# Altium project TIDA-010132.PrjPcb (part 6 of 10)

## Sheet POWER MAIN SHEET1.SchDoc
size 431 x 279 mm; Date: Not shown in title block; ApprovedBy: Not shown in title block; CheckedBy: Not shown in title block; Author: Not shown in title block; CompanyName: Not shown in title block; DrawnBy: Avinash N; Engineer: Not shown in title block; Organization: Not shown in title block; Address1: Not shown in title block; Address2: Not shown in title block; Address3: Not shown in title block; Address4: Not shown in title block; DocumentNumber: 1; Revision: Use project parameter SCH_Rev; SheetNumber: 30; SheetTotal: 32; PageSetup: Record=PageOptions¦CenterHorizontal=True¦CenterVertical=True¦PrintScale=1.00¦XCorrection=1.00¦YCorrection=1.00¦PrintKind=0¦BorderSize=5000000¦LeftOffset=0¦BottomOffset=0¦Orientation=2¦PaperLength=1000¦PaperWidth=1000¦Scale=100¦PaperSource=15¦PrintQuality=600¦MediaType=1¦DitherType=10¦PaperKind=Letter¦PrintScaleMode=1
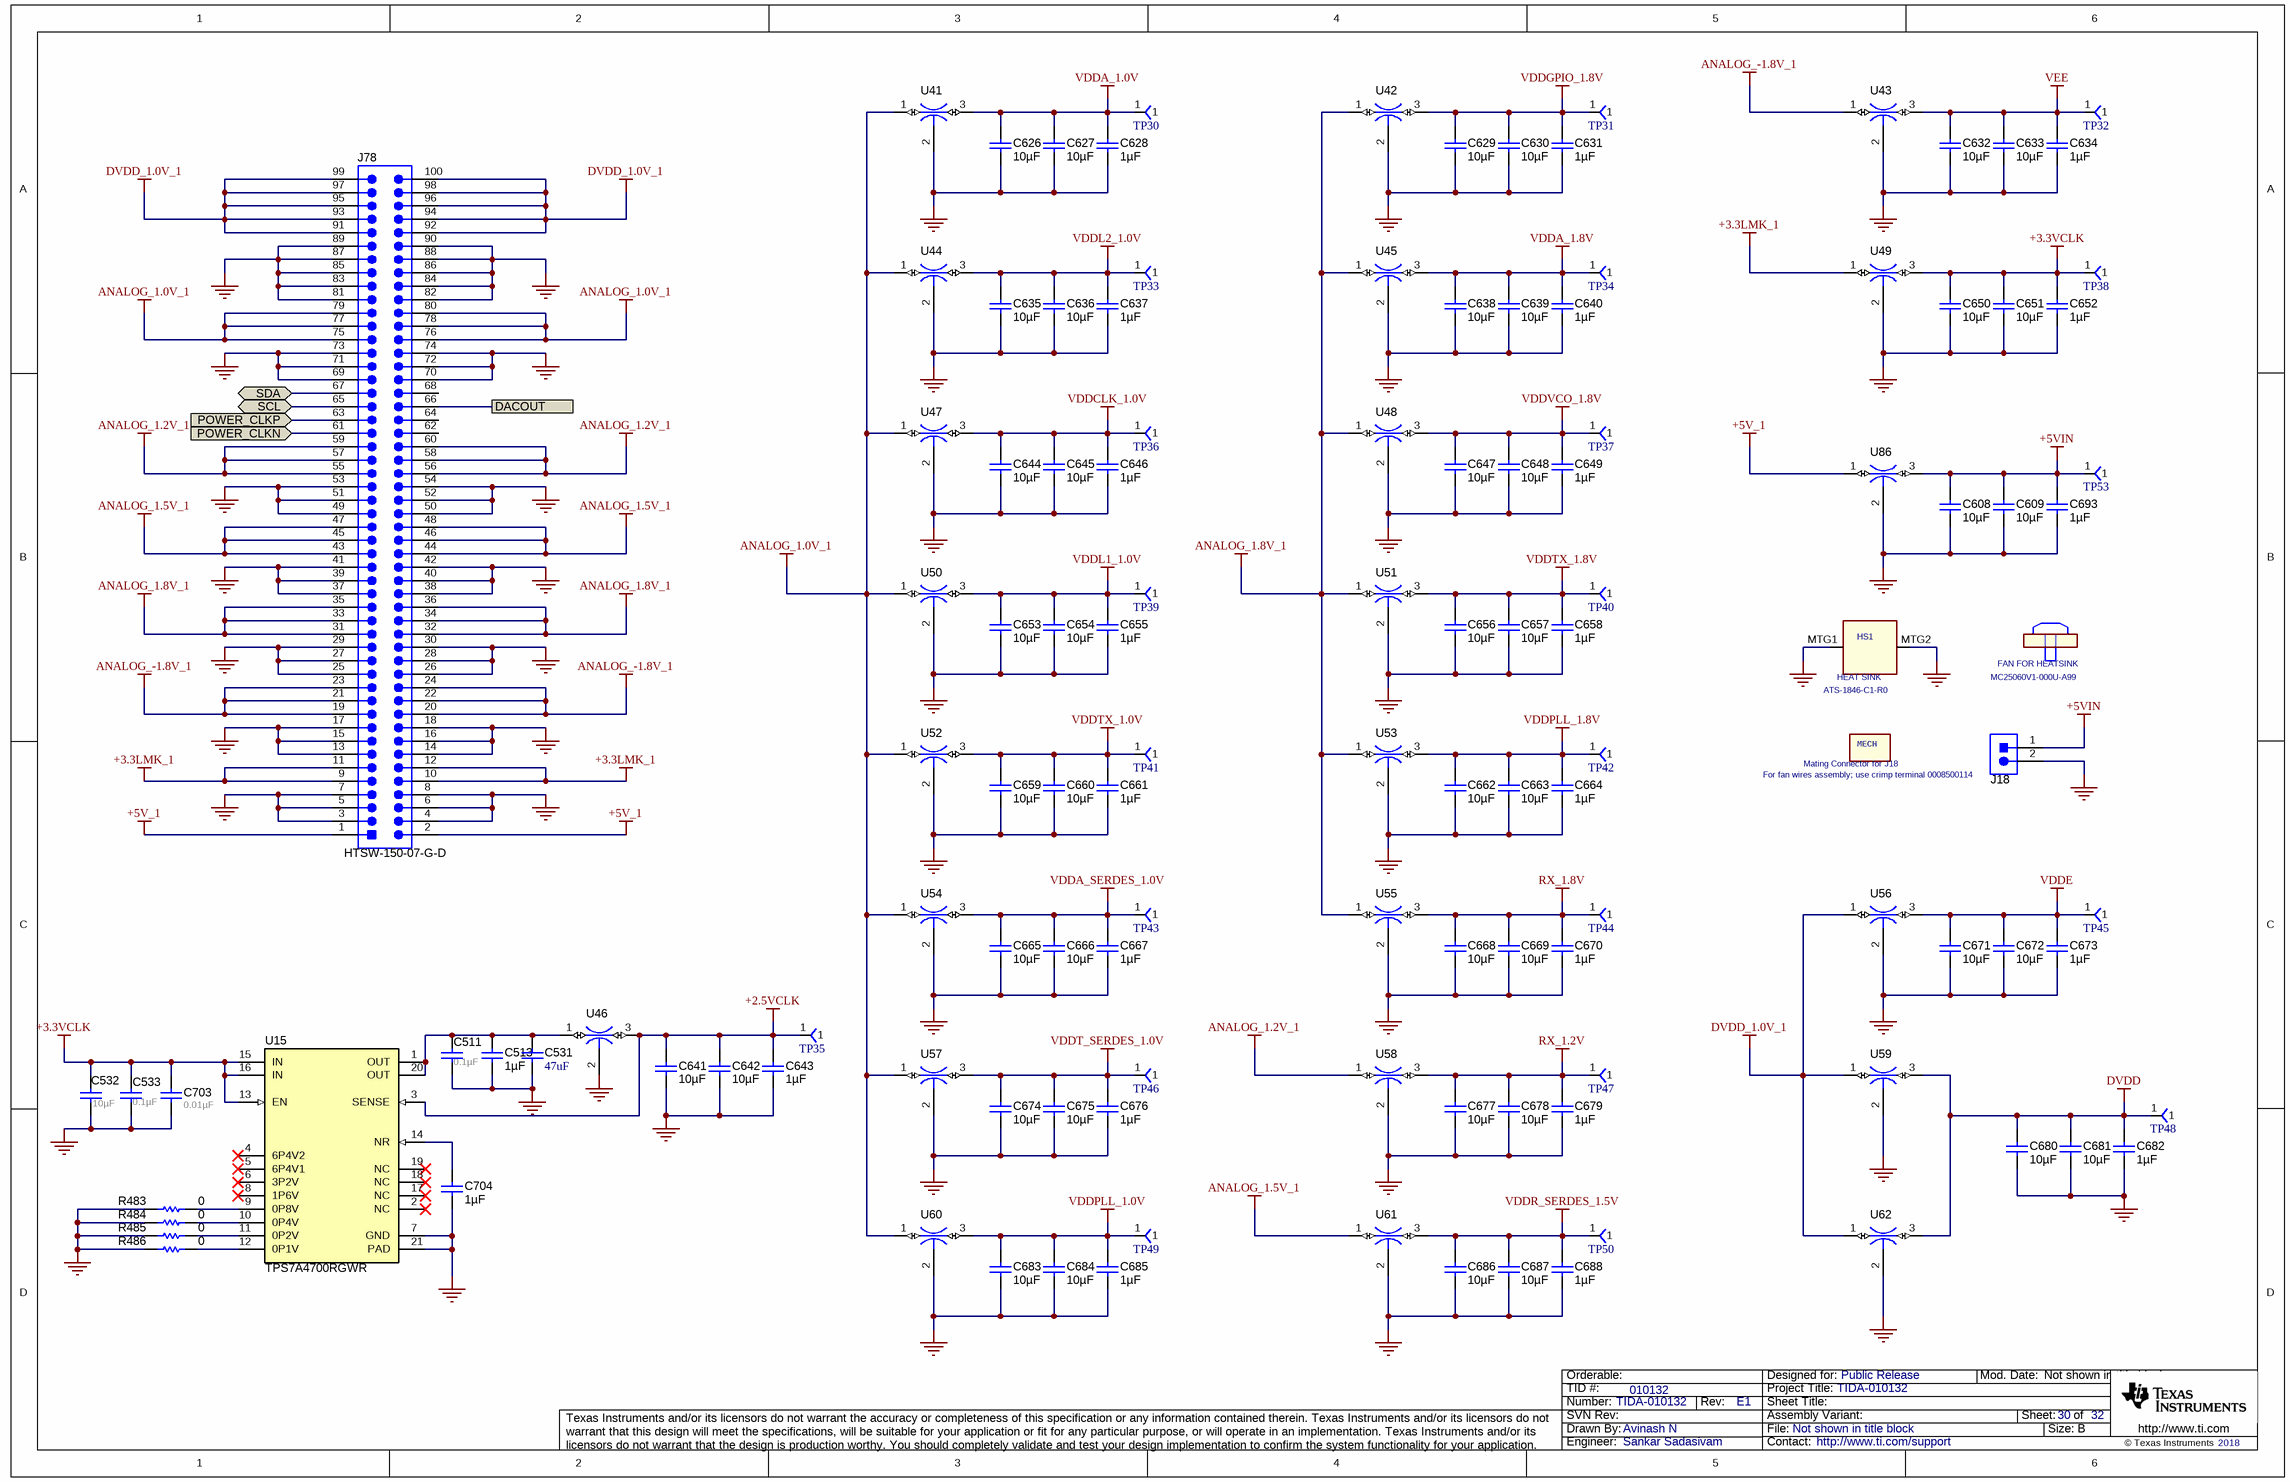
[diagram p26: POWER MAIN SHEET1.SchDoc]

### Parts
C511  ValueDisplayed: 0.1µF  [0603]  (hidden comment: 0603YC104JAT2A)
C513  ValueDisplayed: 1µF  [0603]  (hidden comment: C1608X7R1C105K080AC)
C531  value 47uF  [1210_270]  (hidden comment: GRM32ER61A476KE20L)
C532  ValueDisplayed: 10µF  [0805]  (hidden comment: C0805C106K8PACTU)
C533  ValueDisplayed: 0.1µF  [0603]  (hidden comment: 0603YC104JAT2A)
C608  ValueDisplayed: 10µF  [1206_190]  (hidden comment: C3216X7R1E106M160AE)
C609  ValueDisplayed: 10µF  [1206_190]  (hidden comment: C3216X7R1E106M160AE)
C626  ValueDisplayed: 10µF  [1206_190]  (hidden comment: C3216X7R1E106M160AE)
C627  ValueDisplayed: 10µF  [1206_190]  (hidden comment: C3216X7R1E106M160AE)
C628  ValueDisplayed: 1µF  [0603]  (hidden comment: C1608X7R1C105K080AC)
C629  ValueDisplayed: 10µF  [1206_190]  (hidden comment: C3216X7R1E106M160AE)
C630  ValueDisplayed: 10µF  [1206_190]  (hidden comment: C3216X7R1E106M160AE)
C631  ValueDisplayed: 1µF  [0603]  (hidden comment: C1608X7R1C105K080AC)
C632  ValueDisplayed: 10µF  [1206_190]  (hidden comment: C3216X7R1E106M160AE)
C633  ValueDisplayed: 10µF  [1206_190]  (hidden comment: C3216X7R1E106M160AE)
C634  ValueDisplayed: 1µF  [0603]  (hidden comment: C1608X7R1C105K080AC)
C635  ValueDisplayed: 10µF  [1206_190]  (hidden comment: C3216X7R1E106M160AE)
C636  ValueDisplayed: 10µF  [1206_190]  (hidden comment: C3216X7R1E106M160AE)
C637  ValueDisplayed: 1µF  [0603]  (hidden comment: C1608X7R1C105K080AC)
C638  ValueDisplayed: 10µF  [1206_190]  (hidden comment: C3216X7R1E106M160AE)
C639  ValueDisplayed: 10µF  [1206_190]  (hidden comment: C3216X7R1E106M160AE)
C640  ValueDisplayed: 1µF  [0603]  (hidden comment: C1608X7R1C105K080AC)
C641  ValueDisplayed: 10µF  [1206_190]  (hidden comment: C3216X7R1E106M160AE)
C642  ValueDisplayed: 10µF  [1206_190]  (hidden comment: C3216X7R1E106M160AE)
C643  ValueDisplayed: 1µF  [0603]  (hidden comment: C1608X7R1C105K080AC)
C644  ValueDisplayed: 10µF  [1206_190]  (hidden comment: C3216X7R1E106M160AE)
C645  ValueDisplayed: 10µF  [1206_190]  (hidden comment: C3216X7R1E106M160AE)
C646  ValueDisplayed: 1µF  [0603]  (hidden comment: C1608X7R1C105K080AC)
C647  ValueDisplayed: 10µF  [1206_190]  (hidden comment: C3216X7R1E106M160AE)
C648  ValueDisplayed: 10µF  [1206_190]  (hidden comment: C3216X7R1E106M160AE)
C649  ValueDisplayed: 1µF  [0603]  (hidden comment: C1608X7R1C105K080AC)
C650  ValueDisplayed: 10µF  [1206_190]  (hidden comment: C3216X7R1E106M160AE)
C651  ValueDisplayed: 10µF  [1206_190]  (hidden comment: C3216X7R1E106M160AE)
C652  ValueDisplayed: 1µF  [0603]  (hidden comment: C1608X7R1C105K080AC)
C653  ValueDisplayed: 10µF  [1206_190]  (hidden comment: C3216X7R1E106M160AE)
C654  ValueDisplayed: 10µF  [1206_190]  (hidden comment: C3216X7R1E106M160AE)
C655  ValueDisplayed: 1µF  [0603]  (hidden comment: C1608X7R1C105K080AC)
C656  ValueDisplayed: 10µF  [1206_190]  (hidden comment: C3216X7R1E106M160AE)
C657  ValueDisplayed: 10µF  [1206_190]  (hidden comment: C3216X7R1E106M160AE)
C658  ValueDisplayed: 1µF  [0603]  (hidden comment: C1608X7R1C105K080AC)
C659  ValueDisplayed: 10µF  [1206_190]  (hidden comment: C3216X7R1E106M160AE)
C660  ValueDisplayed: 10µF  [1206_190]  (hidden comment: C3216X7R1E106M160AE)
C661  ValueDisplayed: 1µF  [0603]  (hidden comment: C1608X7R1C105K080AC)
C662  ValueDisplayed: 10µF  [1206_190]  (hidden comment: C3216X7R1E106M160AE)
C663  ValueDisplayed: 10µF  [1206_190]  (hidden comment: C3216X7R1E106M160AE)
C664  ValueDisplayed: 1µF  [0603]  (hidden comment: C1608X7R1C105K080AC)
C665  ValueDisplayed: 10µF  [1206_190]  (hidden comment: C3216X7R1E106M160AE)
C666  ValueDisplayed: 10µF  [1206_190]  (hidden comment: C3216X7R1E106M160AE)
C667  ValueDisplayed: 1µF  [0603]  (hidden comment: C1608X7R1C105K080AC)
C668  ValueDisplayed: 10µF  [1206_190]  (hidden comment: C3216X7R1E106M160AE)
C669  ValueDisplayed: 10µF  [1206_190]  (hidden comment: C3216X7R1E106M160AE)
C670  ValueDisplayed: 1µF  [0603]  (hidden comment: C1608X7R1C105K080AC)
C671  ValueDisplayed: 10µF  [1206_190]  (hidden comment: C3216X7R1E106M160AE)
C672  ValueDisplayed: 10µF  [1206_190]  (hidden comment: C3216X7R1E106M160AE)
C673  ValueDisplayed: 1µF  [0603]  (hidden comment: C1608X7R1C105K080AC)
C674  ValueDisplayed: 10µF  [1206_190]  (hidden comment: C3216X7R1E106M160AE)
C675  ValueDisplayed: 10µF  [1206_190]  (hidden comment: C3216X7R1E106M160AE)
C676  ValueDisplayed: 1µF  [0603]  (hidden comment: C1608X7R1C105K080AC)
C677  ValueDisplayed: 10µF  [1206_190]  (hidden comment: C3216X7R1E106M160AE)
C678  ValueDisplayed: 10µF  [1206_190]  (hidden comment: C3216X7R1E106M160AE)
C679  ValueDisplayed: 1µF  [0603]  (hidden comment: C1608X7R1C105K080AC)
C680  ValueDisplayed: 10µF  [1206_190]  (hidden comment: C3216X7R1E106M160AE)
C681  ValueDisplayed: 10µF  [1206_190]  (hidden comment: C3216X7R1E106M160AE)
C682  ValueDisplayed: 1µF  [0603]  (hidden comment: C1608X7R1C105K080AC)
C683  ValueDisplayed: 10µF  [1206_190]  (hidden comment: C3216X7R1E106M160AE)
C684  ValueDisplayed: 10µF  [1206_190]  (hidden comment: C3216X7R1E106M160AE)
C685  ValueDisplayed: 1µF  [0603]  (hidden comment: C1608X7R1C105K080AC)
C686  ValueDisplayed: 10µF  [1206_190]  (hidden comment: C3216X7R1E106M160AE)
C687  ValueDisplayed: 10µF  [1206_190]  (hidden comment: C3216X7R1E106M160AE)
C688  ValueDisplayed: 1µF  [0603]  (hidden comment: C1608X7R1C105K080AC)
C693  ValueDisplayed: 1µF  [0603]  (hidden comment: C1608X7R1C105K080AC)
C703  ValueDisplayed: 0.01µF  [0402_065]  (hidden comment: 520L103KT16T)
C704  ValueDisplayed: 1µF  [0603]  (hidden comment: C1608X7R1C105K080AC)
CONN_HOUS_1  Mating Connector for J18  Note: For fan wires assembly; use crimp terminal 0008500114  (mechanical)
HS1  HEAT SINK  PartNumber: ATS-1846-C1-R0  [HEATSINK_27X27MM_ATS]
J18  TSW-102-07-T-S  [Samtec_TSW-102-07-T-S]  (value not drawn)
J78  HTSW-150-07-G-D  [Samtec_HTSW-150-07-x-D]
R483  ValueDisplayed: 0  [0402]  (hidden comment: ERJ-2GE0R00X)
R484  ValueDisplayed: 0  [0402]  (hidden comment: ERJ-2GE0R00X)
R485  ValueDisplayed: 0  [0402]  (hidden comment: ERJ-2GE0R00X)
R486  ValueDisplayed: 0  [0402]  (hidden comment: ERJ-2GE0R00X)
TP30  TP-025-SMT  [TP_25MIL-SMT]  (value not drawn)
TP31  TP-025-SMT  [TP_25MIL-SMT]  (value not drawn)
TP32  TP-025-SMT  [TP_25MIL-SMT]  (value not drawn)
TP33  TP-025-SMT  [TP_25MIL-SMT]  (value not drawn)
TP34  TP-025-SMT  [TP_25MIL-SMT]  (value not drawn)
TP35  TP-025-SMT  [TP_25MIL-SMT]  (value not drawn)
TP36  TP-025-SMT  [TP_25MIL-SMT]  (value not drawn)
TP37  TP-025-SMT  [TP_25MIL-SMT]  (value not drawn)
TP38  TP-025-SMT  [TP_25MIL-SMT]  (value not drawn)
TP39  TP-025-SMT  [TP_25MIL-SMT]  (value not drawn)
TP40  TP-025-SMT  [TP_25MIL-SMT]  (value not drawn)
TP41  TP-025-SMT  [TP_25MIL-SMT]  (value not drawn)
TP42  TP-025-SMT  [TP_25MIL-SMT]  (value not drawn)
TP43  TP-025-SMT  [TP_25MIL-SMT]  (value not drawn)
TP44  TP-025-SMT  [TP_25MIL-SMT]  (value not drawn)
TP45  TP-025-SMT  [TP_25MIL-SMT]  (value not drawn)
TP46  TP-025-SMT  [TP_25MIL-SMT]  (value not drawn)
TP47  TP-025-SMT  [TP_25MIL-SMT]  (value not drawn)
TP48  TP-025-SMT  [TP_25MIL-SMT]  (value not drawn)
TP49  TP-025-SMT  [TP_25MIL-SMT]  (value not drawn)
TP50  TP-025-SMT  [TP_25MIL-SMT]  (value not drawn)
TP53  TP-025-SMT  [TP_25MIL-SMT]  (value not drawn)
U15  TPS7A4700RGWR  [RGW0020A]
U41  NFM31PC276B0J3L  [Murata_NFM31P]  (value not drawn)
U42  NFM31PC276B0J3L  [Murata_NFM31P]  (value not drawn)
U43  NFM31PC276B0J3L  [Murata_NFM31P]  (value not drawn)
U44  NFM31PC276B0J3L  [Murata_NFM31P]  (value not drawn)
U45  NFM31PC276B0J3L  [Murata_NFM31P]  (value not drawn)
U46  NFM31PC276B0J3L  [Murata_NFM31P]  (value not drawn)
U47  NFM31PC276B0J3L  [Murata_NFM31P]  (value not drawn)
U48  NFM31PC276B0J3L  [Murata_NFM31P]  (value not drawn)
U49  NFM31PC276B0J3L  [Murata_NFM31P]  (value not drawn)
U50  NFM31PC276B0J3L  [Murata_NFM31P]  (value not drawn)
U51  NFM31PC276B0J3L  [Murata_NFM31P]  (value not drawn)
U52  NFM31PC276B0J3L  [Murata_NFM31P]  (value not drawn)
U53  NFM31PC276B0J3L  [Murata_NFM31P]  (value not drawn)
U54  NFM31PC276B0J3L  [Murata_NFM31P]  (value not drawn)
U55  NFM31PC276B0J3L  [Murata_NFM31P]  (value not drawn)
U56  NFM31PC276B0J3L  [Murata_NFM31P]  (value not drawn)
U57  NFM31PC276B0J3L  [Murata_NFM31P]  (value not drawn)
U58  NFM31PC276B0J3L  [Murata_NFM31P]  (value not drawn)
U59  NFM31PC276B0J3L  [Murata_NFM31P]  (value not drawn)
U60  NFM31PC276B0J3L  [Murata_NFM31P]  (value not drawn)
U61  NFM31PC276B0J3L  [Murata_NFM31P]  (value not drawn)
U62  NFM31PC276B0J3L  [Murata_NFM31P]  (value not drawn)
U86  NFM31PC276B0J3L  [Murata_NFM31P]  (value not drawn)
Z_FANHEATSINK1  FAN FOR HEATSINK  PartNumber: MC25060V1-000U-A99  (mechanical)

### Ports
DACOUT, POWER_CLKN (in), POWER_CLKP (in), SCL (bidir), SDA (bidir)

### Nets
+2.5VCLK: C641.2 C642.2 C643.2 TP35.1 U15.3(SENSE) U46.3
+3.3LMK_1: J78.9 J78.10 J78.11 J78.12 U49.1
+3.3VCLK: C532.2 C533.2 C650.2 C651.2 C652.2 C703.1 TP38.1 U15.13(EN) U15.15(IN) U15.16(IN) U49.3
+5V_1: J78.1 J78.2 U86.1
+5VIN: C608.2 C609.2 C693.2 J18.1 TP53.1 U86.3
ANALOG_1.0V_1: J78.75 J78.76 J78.77 J78.78 J78.79 J78.80 U41.1 U44.1 U47.1 U50.1 U52.1 U54.1 U57.1 U60.1
ANALOG_1.2V_1: J78.55 J78.56 J78.57 J78.58 J78.59 J78.60 U58.1
ANALOG_1.5V_1: J78.43 J78.44 J78.45 J78.46 J78.47 J78.48 U61.1
ANALOG_1.8V_1: J78.31 J78.32 J78.33 J78.34 J78.35 J78.36 U42.1 U45.1 U48.1 U51.1 U53.1 U55.1
ANALOG_-1.8V_1: J78.19 J78.20 J78.21 J78.22 J78.23 J78.24 U43.1
DVDD: C680.2 C681.2 C682.2 TP48.1 U59.3 U62.3
DVDD_1.0V_1: J78.91 J78.92 J78.93 J78.94 J78.95 J78.96 J78.97 J78.98 J78.99 J78.100 U56.1 U59.1 U62.1
GND: C511.1 C513.1 C531.2 C532.1 C533.1 C608.1 C609.1 C626.1 C627.1 C628.1 C629.1 C630.1 C631.1 C632.1 C633.1 C634.1 C635.1 C636.1 C637.1 C638.1 C639.1 C640.1 C641.1 C642.1 C643.1 C644.1 C645.1 C646.1 C647.1 C648.1 C649.1 C650.1 C651.1 C652.1 C653.1 C654.1 C655.1 C656.1 C657.1 C658.1 C659.1 C660.1 C661.1 C662.1 C663.1 C664.1 C665.1 C666.1 C667.1 C668.1 C669.1 C670.1 C671.1 C672.1 C673.1 C674.1 C675.1 C676.1 C677.1 C678.1 C679.1 C680.1 C681.1 C682.1 C683.1 C684.1 C685.1 C686.1 C687.1 C688.1 C693.1 C703.2 C704.1 HS1.MTG1 HS1.MTG2 J18.2 J78.3 J78.4 J78.5 J78.6 J78.7 J78.8 J78.13 J78.14 J78.15 J78.16 J78.17 J78.18 J78.25 J78.26 J78.27 J78.28 J78.29 J78.30 J78.37 J78.38 J78.39 J78.40 J78.41 J78.42 J78.49 J78.50 J78.51 J78.52 J78.53 J78.54 J78.69 J78.70 J78.71 J78.72 J78.73 J78.74 J78.81 J78.82 J78.83 J78.84 J78.85 J78.86 J78.87 J78.88 J78.89 J78.90 R483.1 R484.1 R485.1 R486.1 U15.7(GND) U15.21(PAD) U41.2 U42.2 U43.2 U44.2 U45.2 U46.2 U47.2 U48.2 U49.2 U50.2 U51.2 U52.2 U53.2 U54.2 U55.2 U56.2 U57.2 U58.2 U59.2 U60.2 U61.2 U62.2 U86.2
RX_1.2V: C677.2 C678.2 C679.2 TP47.1 U58.3
RX_1.8V: C668.2 C669.2 C670.2 TP44.1 U55.3
VDDA_1.0V: C626.2 C627.2 C628.2 TP30.1 U41.3
VDDA_1.8V: C638.2 C639.2 C640.2 TP34.1 U45.3
VDDA_SERDES_1.0V: C665.2 C666.2 C667.2 TP43.1 U54.3
VDDCLK_1.0V: C644.2 C645.2 C646.2 TP36.1 U47.3
VDDE: C671.2 C672.2 C673.2 TP45.1 U56.3
VDDGPIO_1.8V: C629.2 C630.2 C631.2 TP31.1 U42.3
VDDL1_1.0V: C653.2 C654.2 C655.2 TP39.1 U50.3
VDDL2_1.0V: C635.2 C636.2 C637.2 TP33.1 U44.3
VDDPLL_1.0V: C683.2 C684.2 C685.2 TP49.1 U60.3
VDDPLL_1.8V: C662.2 C663.2 C664.2 TP42.1 U53.3
VDDR_SERDES_1.5V: C686.2 C687.2 C688.2 TP50.1 U61.3
VDDT_SERDES_1.0V: C674.2 C675.2 C676.2 TP46.1 U57.3
VDDTX_1.0V: C659.2 C660.2 C661.2 TP41.1 U52.3
VDDTX_1.8V: C656.2 C657.2 C658.2 TP40.1 U51.3
VDDVCO_1.8V: C647.2 C648.2 C649.2 TP37.1 U48.3
VEE: C632.2 C633.2 C634.2 TP32.1 U43.3
DACOUT: J78.66 ; port DACOUT
POWER_CLKN: J78.61 ; port POWER_CLKN
POWER_CLKP: J78.63 ; port POWER_CLKP
SCL: J78.65 ; port SCL
SDA: J78.67 ; port SDA
NetC511_2: C511.2 C513.2 C531.1 U15.1(OUT) U15.20(OUT) U46.1
NetC704_2: C704.2 U15.14(NR)
NetR483_2: R483.2 U15.9(0P8V)
NetR484_2: R484.2 U15.10(0P4V)
NetR485_2: R485.2 U15.11(0P2V)
NetR486_2: R486.2 U15.12(0P1V)

Not connected (* = marked no-connect by the designer): J78 62 64 68; U15 2(NC)* 4(6P4V2)* 5(6P4V1)* 6(3P2V)* 8(1P6V)* 17(NC)* 18(NC)* 19(NC)*

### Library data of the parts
C511 C533 = 0603YC104JAT2A: CAP, CERM, 0.1uF, 16V, +/-5%, X7R, 0603; Manufacturer: AVX; ESR_Ohm: 0.039; Polarized: N; TaMax_C: 125; TaMin_C: -55; Tolerance_%: 5; VDC_V: 16; Cap_F: 0.0000001; CompType: Capacitor; Value1: 0.039 ohm; U/M: EA
C513 C628 C631 C634 C637 C640 C643 C646 C649 C652 C655 C658 C661 C664 C667 C670 C673 C676 C679 C682 C685 C688 C693 C704 = C1608X7R1C105K080AC: CAP, CERM, 1 µF, 16 V,+/- 10%, X7R, 0603; Manufacturer: TDK; Polarized: N; CompType: Capacitor; Value: 1uF; U/M: EA; Cap_F: 0.000001; Tolerance_%: 10; ESR_ohm: 0.0057; Value1: 0.0057 ohm; VDC_V: 16; Value2: 16V; TaMin_C: -55; TaMax_C: 125; SizeArea_mm2: 1.28; SizeAreaWB_mm2: 4.68; SizeX_mm: 1.6; SizeY_mm: 0.8; SizeZ_mm: 1; AEC Category: Q200; Green_Lifecycle: Active; Green_REACh: Passed
C531 = CMP-0009208-2: CAP, CERM, 47 uF, 10 V, +/- 10%, X5R, 1210; Manufacturer: MuRata; TaMin_C: -55°C; ESR_ohm: 1m; Polarized: N; SizeAreaWB_mm2: 14.7; Value1: 0.001 ohm; U/M: EA; TaMax_C: 85°C; SizeZ_mm: 2.7; SizeX_mm: 3.2; SizeY_mm: 2.5; Cap_Case: 1210; Value2: 10V; SizeArea_mm2: 8; CompType: Capacitor; Cap_F: 47µF; AEC Category: Q200
C532 = C0805C106K8PACTU: CAP, CERM, 10uF, 10V, +/-10%, X5R, 0805; Manufacturer: Kemet; ESR_Ohm: 0.003; IRMS_A: 11.43; Polarized: N; TaMax_C: 85; TaMin_C: -55; Tolerance_%: 10; Cap_F: 0.00001; CompType: Capacitor; U/M: EA; Value1: 0.003 ohm
C608 C609 C626 C627 C629 C630 C632 C633 C635 C636 C638 C639 C641 C642 C644 C645 C647 C648 C650 C651 C653 C654 C656 C657 C659 C660 C662 C663 C665 C666 C668 C669 C671 C672 C674 C675 C677 C678 C680 C681 C683 C684 C686 C687 = C3216X7R1E106M160AE: CAP, CERM, 10 µF, 25 V, +/- 20%, X7R, 1206_190; Manufacturer: TDK; Polarized: N; CompType: Capacitor; Value: 10uF; U/M: EA; Cap_F: 0.00001; Tolerance_%: 20; Value1: Unknown; VDC_V: 25; Value2: 25V; TaMin_C: -55; TaMax_C: 125; Cap_Case: 1206; SizeArea_mm2: 5.12; SizeAreaWB_mm2: 10.92; SizeX_mm: 3.2; SizeY_mm: 1.6; SizeZ_mm: 1.9; AEC Category: Q200
C703 = 520L103KT16T: CAP, CERM, 0.01 µF, 16 V, +/- 10%, X7R, 0402; Manufacturer: AT Ceramics; Polarized: N; CompType: Capacitor; Value: 0.01uF; U/M: EA; Cap_F: 0.00000001; Tolerance_%: 10; Value1: Unknown; VDC_V: 16; Value2: 16V; TaMin_C: -55; TaMax_C: 125; Cap_Case: 0402; AEC Category: Q200; SizeArea_mm2: 0.5; SizeAreaWB_mm2: 3; SizeX_mm: 1; SizeZ_mm: 0.65
CONN_HOUS_1 = MechPart: CONN HOUS 2POS .100 W/RAMP/RIB; Manufacturer: Molex
HS1 = HEATSINK_1: 1/2 BRICK HEATSINK 58X61X11.4MM; Manufacturer: Advanced Thermal Solutions
J18 = TSW-102-07-T-S: Header, 2.54 mm, 2x1, Tin, TH; Manufacturer: Samtec; SymbolCreator: a0412235; Pitch_mm: 2.54; Gender: Male; Shrouded: N; Row_Count: 1; Current_A: 6.3; Voltage_V: 550; Cert_CSA: Y; Green_Lifecycle: Active; Green_REACh: Passed
J78 = HTSW-150-07-G-D: Header, 2.54mm, 50x2, Gold, TH; Manufacturer: Samtec; SymbolCreator: a0799628; Pitch_mm: 2.54; Gender: Male; Shrouded: N; Row_Count: 2; Cert_CSA: Y; Green_Lifecycle: Active; Green_REACh: Passed
R483-R486 = ERJ-2GE0R00X: RES, 0, 5%, 0.063 W, 0402; Manufacturer: Panasonic; CompType: Resistor; Value: 0; Value_Code: 0000; Tolerance_%: 5; Power_W: 0.063; Value2: 0.063W; VDC_V: 50; TempCo: 600 ppm/C; SizeArea_mm2: 0.5; SizeX_mm: 1; SizeZ_mm: 0.6; EIA_Code: E24; U/M: EA; AEC Category: Q200; Green_Lifecycle: Active; Green_REACh: Passed
TP30-TP50 TP53 = TP-025-SMT: Test Point, O.025"; Manufacturer: STD; Value: STD
U15 = CMP-0066918-2: 36-V, 1-A, 4.17-uVRMS, RF LDO Voltage Regulator, RGW0020A (VQFN-20); Alternate PartNumber: TPS7A4700RGWT; Alternate Manufacturer: Texas Instruments; Green_Lifecycle: Active; SizeAreaWB_mm2: 49.0; Green_REACh: Passed; SizeZ_mm: 1.0; SizeX_mm: 5.0; SizeArea_mm2: 25.0; CompType: IC; AEC Category: Q200; AEC Qualified: N
U41-U62 U86 = NFM31PC276B0J3L: FILTER LC HIGH FREQ 27uF 1206; Manufacturer: MuRata; SymbolCreator: Altium
Z_FANHEATSINK1 = HEATSINK: FAN AXIAL 25X6.9MM 5VDC WIRE; Manufacturer: SUNON

## Sheet POWER MAIN SHEET2.SchDoc
size 431 x 279 mm; Date: Not shown in title block; ApprovedBy: Not shown in title block; CheckedBy: Not shown in title block; Author: Not shown in title block; CompanyName: Not shown in title block; DrawnBy: Avinash N; Engineer: Not shown in title block; Organization: Not shown in title block; Address1: Not shown in title block; Address2: Not shown in title block; Address3: Not shown in title block; Address4: Not shown in title block; DocumentNumber: 1; Revision: Use project parameter SCH_Rev; SheetNumber: 31; SheetTotal: 32; PageSetup: Record=PageOptions¦CenterHorizontal=True¦CenterVertical=True¦PrintScale=1.00¦XCorrection=1.00¦YCorrection=1.00¦PrintKind=0¦BorderSize=5000000¦LeftOffset=0¦BottomOffset=0¦Orientation=2¦PaperLength=1000¦PaperWidth=1000¦Scale=100¦PaperSource=15¦PrintQuality=600¦MediaType=1¦DitherType=10¦PaperKind=Letter¦PrintScaleMode=1
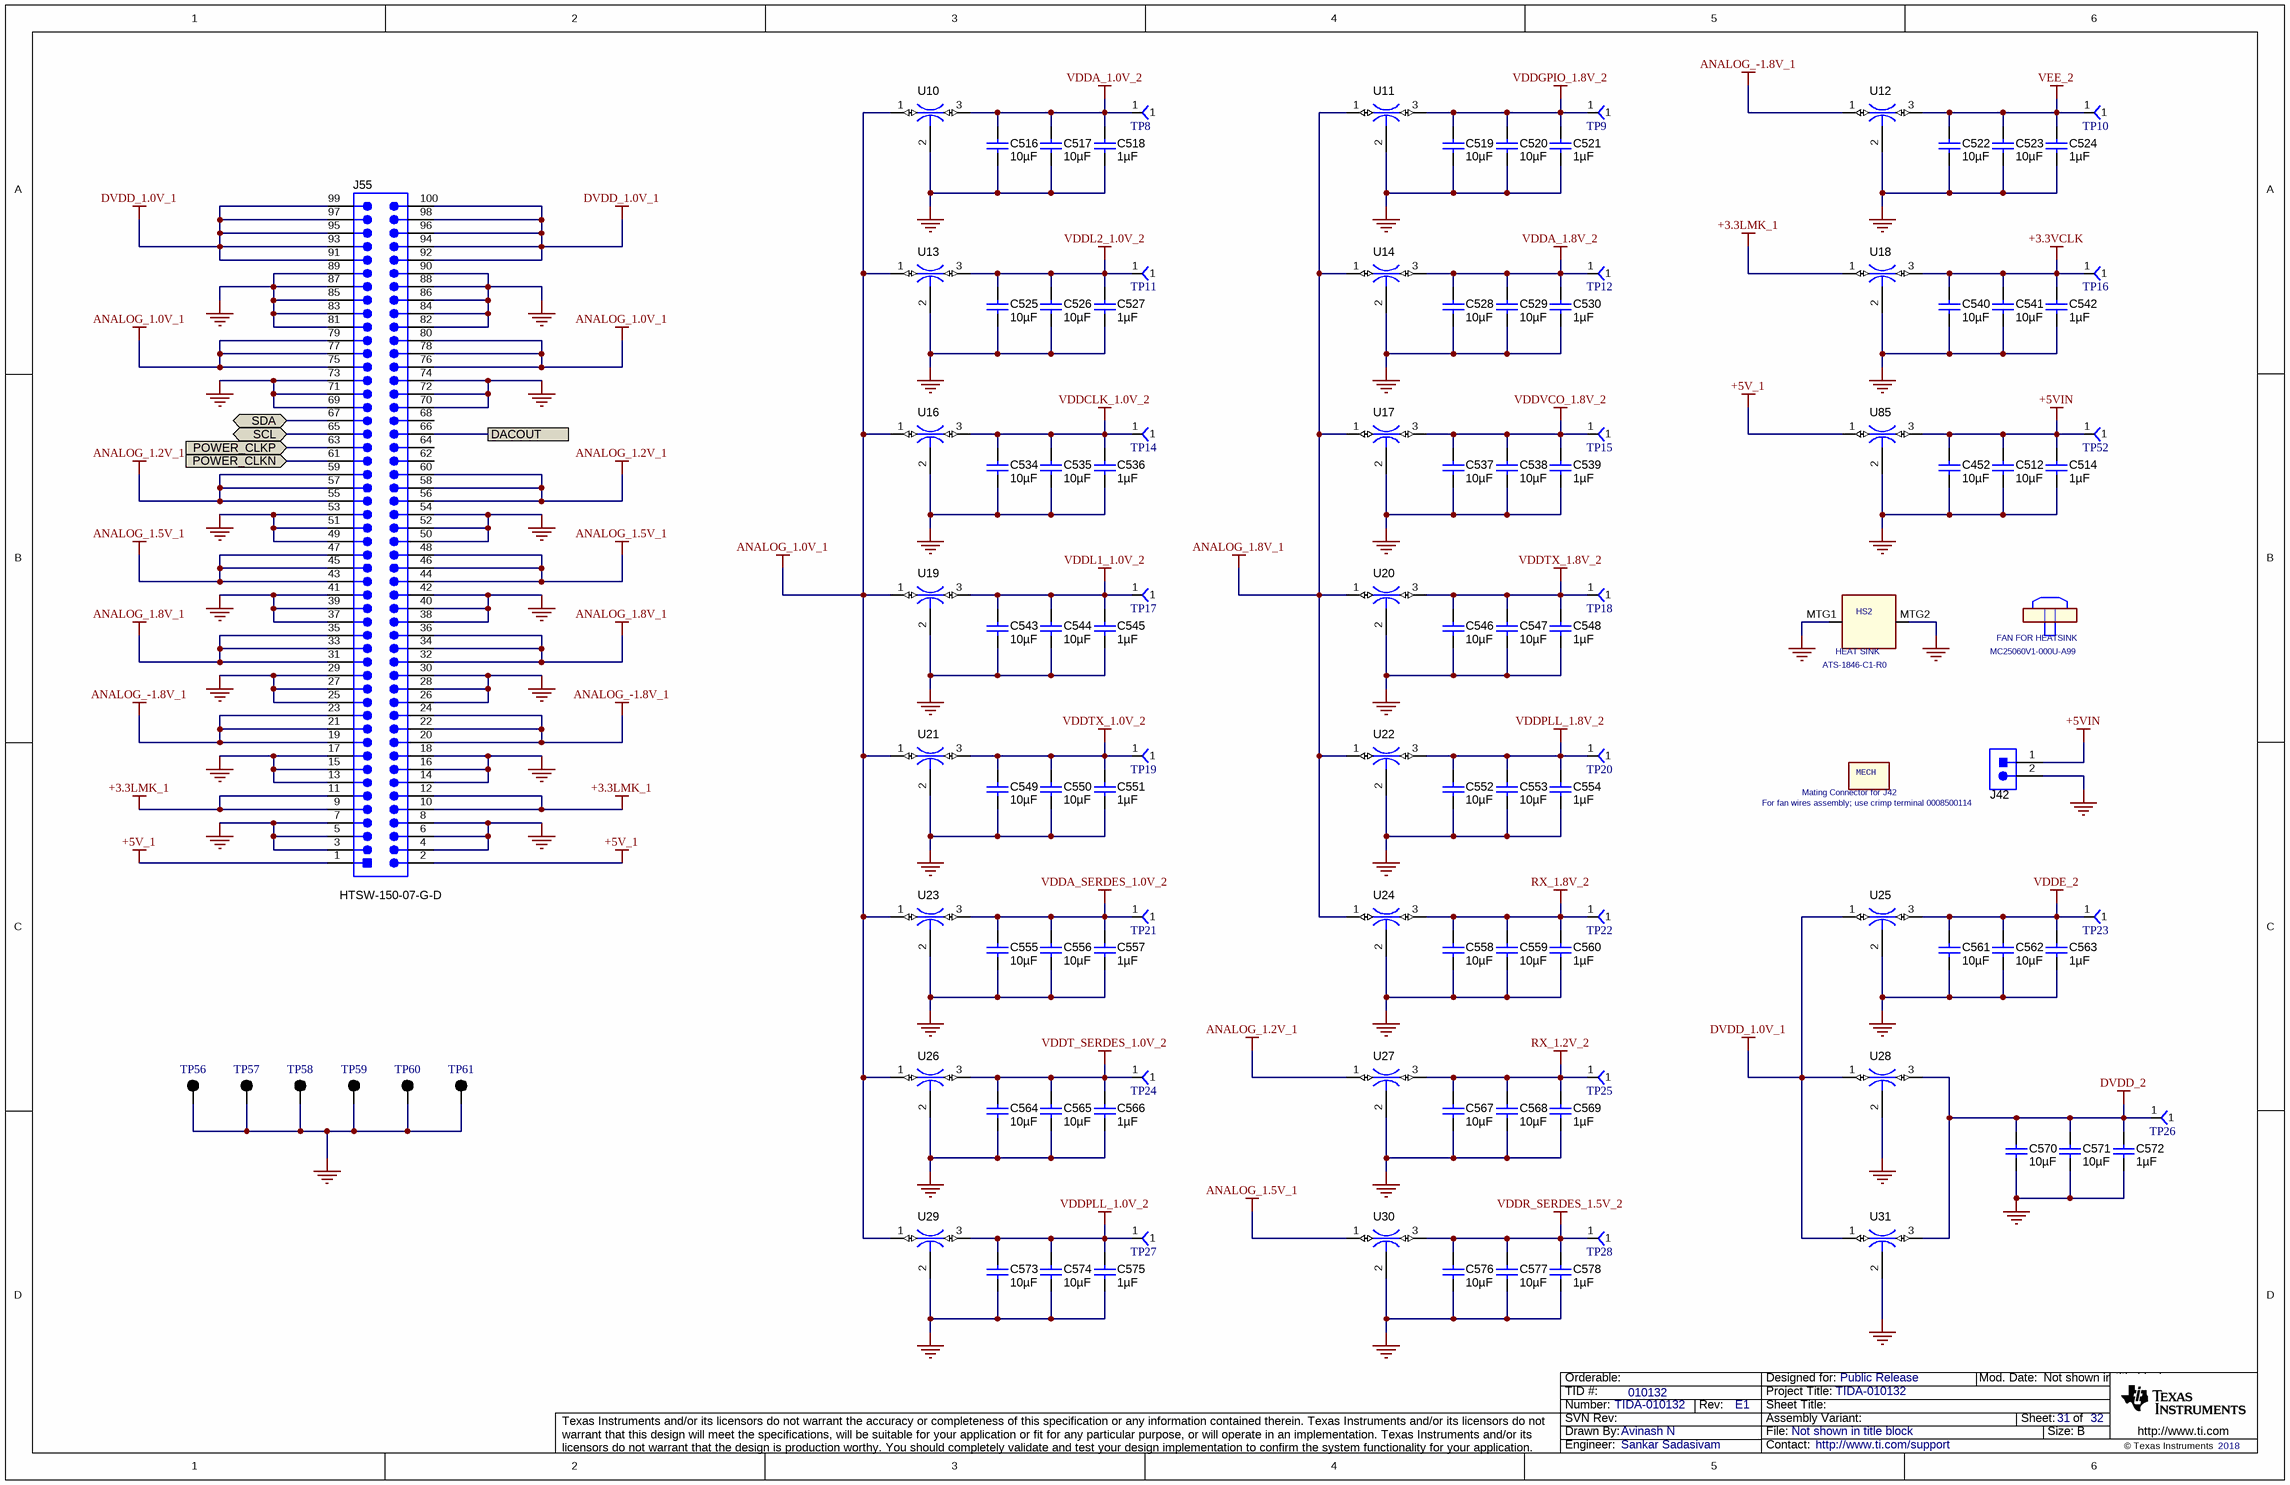
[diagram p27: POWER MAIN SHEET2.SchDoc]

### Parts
C452  ValueDisplayed: 10µF  [1206_190]  (hidden comment: C3216X7R1E106M160AE)
C512  ValueDisplayed: 10µF  [1206_190]  (hidden comment: C3216X7R1E106M160AE)
C514  ValueDisplayed: 1µF  [0603]  (hidden comment: C1608X7R1C105K080AC)
C516  ValueDisplayed: 10µF  [1206_190]  (hidden comment: C3216X7R1E106M160AE)
C517  ValueDisplayed: 10µF  [1206_190]  (hidden comment: C3216X7R1E106M160AE)
C518  ValueDisplayed: 1µF  [0603]  (hidden comment: C1608X7R1C105K080AC)
C519  ValueDisplayed: 10µF  [1206_190]  (hidden comment: C3216X7R1E106M160AE)
C520  ValueDisplayed: 10µF  [1206_190]  (hidden comment: C3216X7R1E106M160AE)
C521  ValueDisplayed: 1µF  [0603]  (hidden comment: C1608X7R1C105K080AC)
C522  ValueDisplayed: 10µF  [1206_190]  (hidden comment: C3216X7R1E106M160AE)
C523  ValueDisplayed: 10µF  [1206_190]  (hidden comment: C3216X7R1E106M160AE)
C524  ValueDisplayed: 1µF  [0603]  (hidden comment: C1608X7R1C105K080AC)
C525  ValueDisplayed: 10µF  [1206_190]  (hidden comment: C3216X7R1E106M160AE)
C526  ValueDisplayed: 10µF  [1206_190]  (hidden comment: C3216X7R1E106M160AE)
C527  ValueDisplayed: 1µF  [0603]  (hidden comment: C1608X7R1C105K080AC)
C528  ValueDisplayed: 10µF  [1206_190]  (hidden comment: C3216X7R1E106M160AE)
C529  ValueDisplayed: 10µF  [1206_190]  (hidden comment: C3216X7R1E106M160AE)
C530  ValueDisplayed: 1µF  [0603]  (hidden comment: C1608X7R1C105K080AC)
C534  ValueDisplayed: 10µF  [1206_190]  (hidden comment: C3216X7R1E106M160AE)
C535  ValueDisplayed: 10µF  [1206_190]  (hidden comment: C3216X7R1E106M160AE)
C536  ValueDisplayed: 1µF  [0603]  (hidden comment: C1608X7R1C105K080AC)
C537  ValueDisplayed: 10µF  [1206_190]  (hidden comment: C3216X7R1E106M160AE)
C538  ValueDisplayed: 10µF  [1206_190]  (hidden comment: C3216X7R1E106M160AE)
C539  ValueDisplayed: 1µF  [0603]  (hidden comment: C1608X7R1C105K080AC)
C540  ValueDisplayed: 10µF  [1206_190]  (hidden comment: C3216X7R1E106M160AE)
C541  ValueDisplayed: 10µF  [1206_190]  (hidden comment: C3216X7R1E106M160AE)
C542  ValueDisplayed: 1µF  [0603]  (hidden comment: C1608X7R1C105K080AC)
C543  ValueDisplayed: 10µF  [1206_190]  (hidden comment: C3216X7R1E106M160AE)
C544  ValueDisplayed: 10µF  [1206_190]  (hidden comment: C3216X7R1E106M160AE)
C545  ValueDisplayed: 1µF  [0603]  (hidden comment: C1608X7R1C105K080AC)
C546  ValueDisplayed: 10µF  [1206_190]  (hidden comment: C3216X7R1E106M160AE)
C547  ValueDisplayed: 10µF  [1206_190]  (hidden comment: C3216X7R1E106M160AE)
C548  ValueDisplayed: 1µF  [0603]  (hidden comment: C1608X7R1C105K080AC)
C549  ValueDisplayed: 10µF  [1206_190]  (hidden comment: C3216X7R1E106M160AE)
C550  ValueDisplayed: 10µF  [1206_190]  (hidden comment: C3216X7R1E106M160AE)
C551  ValueDisplayed: 1µF  [0603]  (hidden comment: C1608X7R1C105K080AC)
C552  ValueDisplayed: 10µF  [1206_190]  (hidden comment: C3216X7R1E106M160AE)
C553  ValueDisplayed: 10µF  [1206_190]  (hidden comment: C3216X7R1E106M160AE)
C554  ValueDisplayed: 1µF  [0603]  (hidden comment: C1608X7R1C105K080AC)
C555  ValueDisplayed: 10µF  [1206_190]  (hidden comment: C3216X7R1E106M160AE)
C556  ValueDisplayed: 10µF  [1206_190]  (hidden comment: C3216X7R1E106M160AE)
C557  ValueDisplayed: 1µF  [0603]  (hidden comment: C1608X7R1C105K080AC)
C558  ValueDisplayed: 10µF  [1206_190]  (hidden comment: C3216X7R1E106M160AE)
C559  ValueDisplayed: 10µF  [1206_190]  (hidden comment: C3216X7R1E106M160AE)
C560  ValueDisplayed: 1µF  [0603]  (hidden comment: C1608X7R1C105K080AC)
C561  ValueDisplayed: 10µF  [1206_190]  (hidden comment: C3216X7R1E106M160AE)
C562  ValueDisplayed: 10µF  [1206_190]  (hidden comment: C3216X7R1E106M160AE)
C563  ValueDisplayed: 1µF  [0603]  (hidden comment: C1608X7R1C105K080AC)
C564  ValueDisplayed: 10µF  [1206_190]  (hidden comment: C3216X7R1E106M160AE)
C565  ValueDisplayed: 10µF  [1206_190]  (hidden comment: C3216X7R1E106M160AE)
C566  ValueDisplayed: 1µF  [0603]  (hidden comment: C1608X7R1C105K080AC)
C567  ValueDisplayed: 10µF  [1206_190]  (hidden comment: C3216X7R1E106M160AE)
C568  ValueDisplayed: 10µF  [1206_190]  (hidden comment: C3216X7R1E106M160AE)
C569  ValueDisplayed: 1µF  [0603]  (hidden comment: C1608X7R1C105K080AC)
C570  ValueDisplayed: 10µF  [1206_190]  (hidden comment: C3216X7R1E106M160AE)
C571  ValueDisplayed: 10µF  [1206_190]  (hidden comment: C3216X7R1E106M160AE)
C572  ValueDisplayed: 1µF  [0603]  (hidden comment: C1608X7R1C105K080AC)
C573  ValueDisplayed: 10µF  [1206_190]  (hidden comment: C3216X7R1E106M160AE)
C574  ValueDisplayed: 10µF  [1206_190]  (hidden comment: C3216X7R1E106M160AE)
C575  ValueDisplayed: 1µF  [0603]  (hidden comment: C1608X7R1C105K080AC)
C576  ValueDisplayed: 10µF  [1206_190]  (hidden comment: C3216X7R1E106M160AE)
C577  ValueDisplayed: 10µF  [1206_190]  (hidden comment: C3216X7R1E106M160AE)
C578  ValueDisplayed: 1µF  [0603]  (hidden comment: C1608X7R1C105K080AC)
CONN_HOUS_2  Mating Connector for J42  Note: For fan wires assembly; use crimp terminal 0008500114  (mechanical)
HS2  HEAT SINK  PartNumber: ATS-1846-C1-R0  [HEATSINK_27X27MM_ATS]
J42  TSW-102-07-T-S  [Samtec_TSW-102-07-T-S]  (value not drawn)
J55  HTSW-150-07-G-D  [Samtec_HTSW-150-07-x-D]
TP8  TP-025-SMT  [TP_25MIL-SMT]  (value not drawn)
TP9  TP-025-SMT  [TP_25MIL-SMT]  (value not drawn)
TP10  TP-025-SMT  [TP_25MIL-SMT]  (value not drawn)
TP11  TP-025-SMT  [TP_25MIL-SMT]  (value not drawn)
TP12  TP-025-SMT  [TP_25MIL-SMT]  (value not drawn)
TP14  TP-025-SMT  [TP_25MIL-SMT]  (value not drawn)
TP15  TP-025-SMT  [TP_25MIL-SMT]  (value not drawn)
TP16  TP-025-SMT  [TP_25MIL-SMT]  (value not drawn)
TP17  TP-025-SMT  [TP_25MIL-SMT]  (value not drawn)
TP18  TP-025-SMT  [TP_25MIL-SMT]  (value not drawn)
TP19  TP-025-SMT  [TP_25MIL-SMT]  (value not drawn)
TP20  TP-025-SMT  [TP_25MIL-SMT]  (value not drawn)
TP21  TP-025-SMT  [TP_25MIL-SMT]  (value not drawn)
TP22  TP-025-SMT  [TP_25MIL-SMT]  (value not drawn)
TP23  TP-025-SMT  [TP_25MIL-SMT]  (value not drawn)
TP24  TP-025-SMT  [TP_25MIL-SMT]  (value not drawn)
TP25  TP-025-SMT  [TP_25MIL-SMT]  (value not drawn)
TP26  TP-025-SMT  [TP_25MIL-SMT]  (value not drawn)
TP27  TP-025-SMT  [TP_25MIL-SMT]  (value not drawn)
TP28  TP-025-SMT  [TP_25MIL-SMT]  (value not drawn)
TP52  TP-025-SMT  [TP_25MIL-SMT]  (value not drawn)
TP56  5001  [Keystone5001]  (value not drawn)
TP57  5001  [Keystone5001]  (value not drawn)
TP58  5001  [Keystone5001]  (value not drawn)
TP59  5001  [Keystone5001]  (value not drawn)
TP60  5001  [Keystone5001]  (value not drawn)
TP61  5001  [Keystone5001]  (value not drawn)
U10  NFM31PC276B0J3L  [Murata_NFM31P]  (value not drawn)
U11  NFM31PC276B0J3L  [Murata_NFM31P]  (value not drawn)
U12  NFM31PC276B0J3L  [Murata_NFM31P]  (value not drawn)
U13  NFM31PC276B0J3L  [Murata_NFM31P]  (value not drawn)
U14  NFM31PC276B0J3L  [Murata_NFM31P]  (value not drawn)
U16  NFM31PC276B0J3L  [Murata_NFM31P]  (value not drawn)
U17  NFM31PC276B0J3L  [Murata_NFM31P]  (value not drawn)
U18  NFM31PC276B0J3L  [Murata_NFM31P]  (value not drawn)
U19  NFM31PC276B0J3L  [Murata_NFM31P]  (value not drawn)
U20  NFM31PC276B0J3L  [Murata_NFM31P]  (value not drawn)
U21  NFM31PC276B0J3L  [Murata_NFM31P]  (value not drawn)
U22  NFM31PC276B0J3L  [Murata_NFM31P]  (value not drawn)
U23  NFM31PC276B0J3L  [Murata_NFM31P]  (value not drawn)
U24  NFM31PC276B0J3L  [Murata_NFM31P]  (value not drawn)
U25  NFM31PC276B0J3L  [Murata_NFM31P]  (value not drawn)
U26  NFM31PC276B0J3L  [Murata_NFM31P]  (value not drawn)
U27  NFM31PC276B0J3L  [Murata_NFM31P]  (value not drawn)
U28  NFM31PC276B0J3L  [Murata_NFM31P]  (value not drawn)
U29  NFM31PC276B0J3L  [Murata_NFM31P]  (value not drawn)
U30  NFM31PC276B0J3L  [Murata_NFM31P]  (value not drawn)
U31  NFM31PC276B0J3L  [Murata_NFM31P]  (value not drawn)
U85  NFM31PC276B0J3L  [Murata_NFM31P]  (value not drawn)
Z_FANHEATSINK2  FAN FOR HEATSINK  PartNumber: MC25060V1-000U-A99  (mechanical)

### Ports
DACOUT, POWER_CLKN (in), POWER_CLKP (in), SCL (bidir), SDA (bidir)

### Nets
+3.3LMK_1: J55.9 J55.10 J55.11 J55.12 U18.1
+3.3VCLK: C540.2 C541.2 C542.2 TP16.1 U18.3
+5V_1: J55.1 J55.2 U85.1
+5VIN: C452.2 C512.2 C514.2 J42.1 TP52.1 U85.3
ANALOG_1.0V_1: J55.75 J55.76 J55.77 J55.78 J55.79 J55.80 U10.1 U13.1 U16.1 U19.1 U21.1 U23.1 U26.1 U29.1
ANALOG_1.2V_1: J55.55 J55.56 J55.57 J55.58 J55.59 J55.60 U27.1
ANALOG_1.5V_1: J55.43 J55.44 J55.45 J55.46 J55.47 J55.48 U30.1
ANALOG_1.8V_1: J55.31 J55.32 J55.33 J55.34 J55.35 J55.36 U11.1 U14.1 U17.1 U20.1 U22.1 U24.1
ANALOG_-1.8V_1: J55.19 J55.20 J55.21 J55.22 J55.23 J55.24 U12.1
DVDD_1.0V_1: J55.91 J55.92 J55.93 J55.94 J55.95 J55.96 J55.97 J55.98 J55.99 J55.100 U25.1 U28.1 U31.1
DVDD_2: C570.2 C571.2 C572.2 TP26.1 U28.3 U31.3
GND: C452.1 C512.1 C514.1 C516.1 C517.1 C518.1 C519.1 C520.1 C521.1 C522.1 C523.1 C524.1 C525.1 C526.1 C527.1 C528.1 C529.1 C530.1 C534.1 C535.1 C536.1 C537.1 C538.1 C539.1 C540.1 C541.1 C542.1 C543.1 C544.1 C545.1 C546.1 C547.1 C548.1 C549.1 C550.1 C551.1 C552.1 C553.1 C554.1 C555.1 C556.1 C557.1 C558.1 C559.1 C560.1 C561.1 C562.1 C563.1 C564.1 C565.1 C566.1 C567.1 C568.1 C569.1 C570.1 C571.1 C572.1 C573.1 C574.1 C575.1 C576.1 C577.1 C578.1 HS2.MTG1 HS2.MTG2 J42.2 J55.3 J55.4 J55.5 J55.6 J55.7 J55.8 J55.13 J55.14 J55.15 J55.16 J55.17 J55.18 J55.25 J55.26 J55.27 J55.28 J55.29 J55.30 J55.37 J55.38 J55.39 J55.40 J55.41 J55.42 J55.49 J55.50 J55.51 J55.52 J55.53 J55.54 J55.69 J55.70 J55.71 J55.72 J55.73 J55.74 J55.81 J55.82 J55.83 J55.84 J55.85 J55.86 J55.87 J55.88 J55.89 J55.90 TP56.1 TP57.1 TP58.1 TP59.1 TP60.1 TP61.1 U10.2 U11.2 U12.2 U13.2 U14.2 U16.2 U17.2 U18.2 U19.2 U20.2 U21.2 U22.2 U23.2 U24.2 U25.2 U26.2 U27.2 U28.2 U29.2 U30.2 U31.2 U85.2
RX_1.2V_2: C567.2 C568.2 C569.2 TP25.1 U27.3
RX_1.8V_2: C558.2 C559.2 C560.2 TP22.1 U24.3
VDDA_1.0V_2: C516.2 C517.2 C518.2 TP8.1 U10.3
VDDA_1.8V_2: C528.2 C529.2 C530.2 TP12.1 U14.3
VDDA_SERDES_1.0V_2: C555.2 C556.2 C557.2 TP21.1 U23.3
VDDCLK_1.0V_2: C534.2 C535.2 C536.2 TP14.1 U16.3
VDDE_2: C561.2 C562.2 C563.2 TP23.1 U25.3
VDDGPIO_1.8V_2: C519.2 C520.2 C521.2 TP9.1 U11.3
VDDL1_1.0V_2: C543.2 C544.2 C545.2 TP17.1 U19.3
VDDL2_1.0V_2: C525.2 C526.2 C527.2 TP11.1 U13.3
VDDPLL_1.0V_2: C573.2 C574.2 C575.2 TP27.1 U29.3
VDDPLL_1.8V_2: C552.2 C553.2 C554.2 TP20.1 U22.3
VDDR_SERDES_1.5V_2: C576.2 C577.2 C578.2 TP28.1 U30.3
VDDT_SERDES_1.0V_2: C564.2 C565.2 C566.2 TP24.1 U26.3
VDDTX_1.0V_2: C549.2 C550.2 C551.2 TP19.1 U21.3
VDDTX_1.8V_2: C546.2 C547.2 C548.2 TP18.1 U20.3
VDDVCO_1.8V_2: C537.2 C538.2 C539.2 TP15.1 U17.3
VEE_2: C522.2 C523.2 C524.2 TP10.1 U12.3
DACOUT: J55.66 ; port DACOUT
POWER_CLKN: J55.61 ; port POWER_CLKN
POWER_CLKP: J55.63 ; port POWER_CLKP
SCL: J55.65 ; port SCL
SDA: J55.67 ; port SDA

Not connected (* = marked no-connect by the designer): J55 62 64 68

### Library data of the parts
C452 C512 C516 C517 C519 C520 C522 C523 C525 C526 C528 C529 C534 C535 C537 C538 C540 C541 C543 C544 C546 C547 C549 C550 C552 C553 C555 C556 C558 C559 C561 C562 C564 C565 C567 C568 C570 C571 C573 C574 C576 C577 = C3216X7R1E106M160AE: as C608 on sheet POWER MAIN SHEET1
C514 C518 C521 C524 C527 C530 C536 C539 C542 C545 C548 C551 C554 C557 C560 C563 C566 C569 C572 C575 C578 = C1608X7R1C105K080AC: as C513 on sheet POWER MAIN SHEET1
CONN_HOUS_2 = MechPart: as CONN_HOUS_1 on sheet POWER MAIN SHEET1
HS2 = HEATSINK_1: as HS1 on sheet POWER MAIN SHEET1
J42 = TSW-102-07-T-S: as J18 on sheet POWER MAIN SHEET1
J55 = HTSW-150-07-G-D: as J78 on sheet POWER MAIN SHEET1
TP8-TP12 TP14-TP28 TP52 = TP-025-SMT: as TP30-TP50 on sheet POWER MAIN SHEET1
TP56-TP61 = 5001: Test Point, Miniature, Black, TH; Manufacturer: Keystone; CompType: Test Point Loop; ContactFinish: Silver; Green_Lifecycle: Active; Green_REACh: Passed
U10-U14 U16-U31 U85 = NFM31PC276B0J3L: as U41 on sheet POWER MAIN SHEET1
Z_FANHEATSINK2 = HEATSINK: as Z_FANHEATSINK1 on sheet POWER MAIN SHEET1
